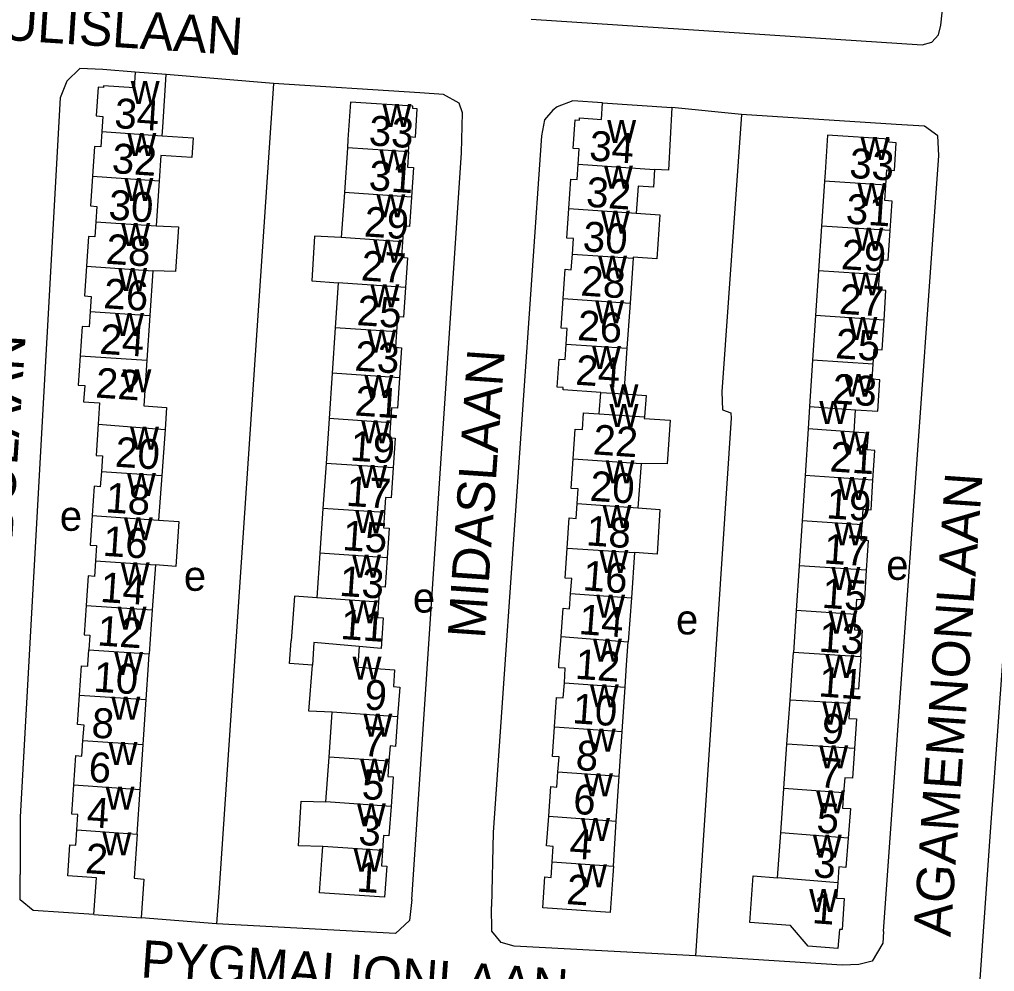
# Model space of a CAD drawing. Extents: x 161773 to 163836, y 384796 to 386521.
# Drawn here: x 162100.7 to 162231.1, y 385459 to 385586.3 of the extents above; entities that cross this region are included whole.
import ezdxf

# ---------------------------------------------------------------- set-up
doc = ezdxf.new("R2010")
doc.units = 0
for name, color, linetype in [('BLT_Basislijn', 7, 'Continuous'), ('BLT_Bebouwing', 7, 'Continuous'), ('BLT_Centroide', 7, 'Continuous'), ('BLT_Huisnummer', 7, 'Continuous'), ('BLT_Huisnummer_ tussenligend', 7, 'Continuous'), ('BLT_Onderverdeling_panden', 7, 'Continuous'), ('BLT_Straatnaam', 7, 'Continuous')]:
    doc.layers.add(name, color=color, linetype=linetype)

msp = doc.modelspace()

# ---------------------------------------------------------------- linework, layer by layer
at = {"layer": 'BLT_Basislijn'}
for p, q in [((162134.64, 385577.69), (162127.4, 385470.16)), ((162230.63, 385478.94), (162230.98, 385483.73)), ((162229.61, 385464.38), (162230.63, 385478.94)), ((162127.4, 385470.16), (162127.01, 385465.4)), ((162227.1, 385428.51), (162229.61, 385464.38))]:
    msp.add_line(p, q, dxfattribs=at)
for points in [[(162169.1, 385586.33), (162221.38, 385582.88), (162222.67, 385583.23), (162223.56, 385584.21), (162223.9, 385585.5), (162224.18, 385588.39), (162225.39, 385606.24)], [(162116.15, 385579.21), (162111.84, 385579.56), (162108.77, 385579.7), (162106.99, 385578.01), (162106.1, 385575.79), (162100.77, 385479.69), (162100.75, 385471.99)], [(162134.64, 385577.69), (162120.31, 385578.93)], [(162159.92, 385573.8), (162159.47, 385575.09), (162157.4, 385576.26), (162154.2, 385576.48), (162134.64, 385577.69)], [(162178.64, 385575.12), (162174.67, 385575.38), (162172.6, 385574.61), (162172, 385574.16), (162170.89, 385572.86), (162170.47, 385570.73)], [(162197.21, 385573.57), (162187.91, 385574.49)], [(162153.13, 385468.63), (162159.77, 385568.46), (162159.92, 385573.8)], [(162197.21, 385573.57), (162194.59, 385536.51), (162194.7, 385534.11), (162195.8, 385533.7), (162195.83, 385532.98), (162191.08, 385461.11)], [(162223.46, 385570.7), (162221.71, 385572), (162217.92, 385572.25), (162197.21, 385573.57)], [(162170.47, 385570.73), (162164.04, 385477.58), (162163.78, 385467.71)], [(162216.22, 385464.38), (162223.62, 385568.08), (162223.46, 385570.7)], [(162230.98, 385483.73), (162234.59, 385533.9), (162235.86, 385535.65), (162236.97, 385536.24)], [(162110.62, 385466.63), (162102.51, 385467.15), (162100.77, 385468.61), (162100.75, 385471.99)], [(162153.13, 385468.63), (162152.85, 385465.84), (162150.95, 385464.11), (162127.01, 385465.4)], [(162191.08, 385461.11), (162166.85, 385462.41), (162165.1, 385462.88), (162163.83, 385464.41), (162163.78, 385467.71)], [(162127.01, 385465.4), (162116.94, 385466.21)], [(162216.22, 385464.38), (162216.14, 385462.79), (162214.71, 385460.4), (162212.93, 385459.94), (162210.69, 385459.84), (162191.08, 385461.11)]]:
    msp.add_lwpolyline(points, dxfattribs=at)
at = {"layer": 'BLT_Bebouwing'}
for p, q in [((162144.52, 385569.12), (162144.12, 385563.13)), ((162119.35, 385564.72), (162118.94, 385558.7)), ((162208.32, 385564.64), (162207.93, 385558.65)), ((162144.12, 385563.13), (162143.71, 385557.12)), ((162207.93, 385558.65), (162207.53, 385552.66)), ((162182.73, 385554.35), (162182.32, 385548.34)), ((162118.53, 385552.68), (162118.13, 385546.68)), ((162207.53, 385552.66), (162207.14, 385546.68)), ((162143.3, 385551.07), (162142.9, 385545.05)), ((162182.32, 385548.34), (162181.91, 385542.34)), ((162118.13, 385546.68), (162117.73, 385540.72)), ((162207.14, 385546.68), (162206.74, 385540.72)), ((162142.9, 385545.05), (162142.48, 385538.97)), ((162181.91, 385542.34), (162181.5, 385536.21)), ((162117.73, 385540.72), (162117.31, 385534.62)), ((162206.74, 385540.72), (162206.34, 385534.54)), ((162142.48, 385538.97), (162142.07, 385532.92)), ((162178.21, 385533.56), (162178.4, 385536.42)), ((162111.4, 385535.02), (162111.2, 385532.17)), ((162206.34, 385534.54), (162206.14, 385531.57)), ((162212.39, 385532.61), (162212.49, 385534.11)), ((162142.07, 385532.92), (162141.67, 385526.92)), ((162206.14, 385531.57), (162205.73, 385525.3)), ((162141.67, 385526.92), (162141.26, 385520.92)), ((162183.8, 385526.93), (162183.38, 385521)), ((162119.71, 385525.32), (162119.29, 385519.35)), ((162205.73, 385525.3), (162205.33, 385519.26)), ((162141.26, 385520.92), (162140.86, 385514.94)), ((162205.33, 385519.26), (162204.93, 385513.25)), ((162140.86, 385514.94), (162140.45, 385508.94)), ((162182.94, 385515), (162182.51, 385508.97)), ((162118.87, 385513.35), (162118.44, 385507.34)), ((162204.93, 385513.25), (162204.53, 385507.26)), ((162182.51, 385508.97), (162182.09, 385503.1)), ((162118.44, 385507.34), (162118.03, 385501.46)), ((162204.53, 385507.26), (162204.16, 385501.67)), ((162181.28, 385491.09), (162181.67, 385497.02)), ((162117.21, 385489.34), (162117.61, 385495.35)), ((162203.31, 385489.42), (162203.72, 385495.27)), ((162142.07, 385487.68), (162142.48, 385493.68)), ((162180.88, 385485.12), (162181.28, 385491.09)), ((162116.81, 385483.36), (162117.21, 385489.34)), ((162202.89, 385483.47), (162203.31, 385489.42)), ((162141.65, 385481.69), (162142.07, 385487.68)), ((162180.49, 385479.13), (162180.88, 385485.12)), ((162116.41, 385477.39), (162116.81, 385483.36)), ((162202.47, 385477.56), (162202.89, 385483.47)), ((162180.09, 385473.09), (162180.49, 385479.13)), ((162202.04, 385471.54), (162202.47, 385477.56)), ((162149.5, 385468.95), (162140.81, 385469.55)), ((162179.68, 385466.9), (162170.64, 385467.53)), ((162110.62, 385466.63), (162116.94, 385466.21))]:
    msp.add_line(p, q, dxfattribs=at)
for points in [[(162116.15, 385579.21), (162116.01, 385577.14), (162111.92, 385577.42), (162111.9, 385577.18), (162111.21, 385577.23), (162110.95, 385573.37), (162111.83, 385573.31), (162111.69, 385571.28)], [(162120.31, 385578.93), (162116.15, 385579.21)], [(162119.75, 385570.73), (162119.83, 385571.87), (162120.31, 385578.93)], [(162152.7, 385568.57), (162152.83, 385570.61), (162153.62, 385570.55), (162153.88, 385574.34), (162153.28, 385574.38), (162153.3, 385574.66), (162144.94, 385575.23), (162144.6, 385570.24), (162144.52, 385569.12)], [(162175.39, 385566.92), (162175.53, 385568.97), (162174.71, 385569.03), (162174.97, 385572.87), (162175.56, 385572.83), (162175.58, 385573.11), (162178.49, 385572.91), (162178.64, 385575.12)], [(162178.64, 385575.12), (162187.91, 385574.49)], [(162187.91, 385574.49), (162187.46, 385566.12), (162185.61, 385566.22)], [(162111.69, 385571.28), (162111.55, 385569.24), (162110.73, 385569.29), (162110.46, 385565.32)], [(162119.75, 385570.73), (162123.91, 385570.45), (162123.73, 385567.8), (162119.57, 385568.08), (162119.35, 385564.72)], [(162216.52, 385564.1), (162216.66, 385566.15), (162217.68, 385566.09), (162217.93, 385569.79), (162216.93, 385569.86), (162216.96, 385570.27), (162208.73, 385570.82), (162208.4, 385565.83), (162208.32, 385564.64)], [(162152.7, 385568.57), (162152.56, 385566.52), (162153.35, 385566.47), (162153.09, 385562.53)], [(162174.14, 385560.98), (162174.41, 385564.93), (162175.26, 385564.87), (162175.39, 385566.92)], [(162185.61, 385566.22), (162185.45, 385563.85), (162183.39, 385563.99), (162183.14, 385560.37)], [(162110.46, 385565.32), (162110.19, 385561.35), (162111.04, 385561.29), (162110.9, 385559.24)], [(162217.11, 385558.04), (162217.37, 385561.99), (162216.39, 385562.05), (162216.52, 385564.1)], [(162153.09, 385562.53), (162152.82, 385558.59), (162152.03, 385558.64), (162151.89, 385556.56)], [(162174.61, 385554.9), (162174.75, 385556.98), (162173.87, 385557.04), (162174.14, 385560.98)], [(162183.14, 385560.37), (162186.3, 385560.16), (162185.9, 385554.29), (162182.74, 385554.5), (162182.73, 385554.35)], [(162110.9, 385559.24), (162110.76, 385557.2), (162109.9, 385557.26), (162109.64, 385553.29)], [(162118.94, 385558.7), (162121.94, 385558.53), (162121.56, 385552.56), (162118.53, 385552.68)], [(162143.71, 385557.12), (162140.14, 385557.32), (162139.77, 385551.35), (162143.3, 385551.07)], [(162215.67, 385552.12), (162215.81, 385554.16), (162216.84, 385554.09), (162217.11, 385558.04)], [(162151.89, 385556.56), (162151.75, 385554.49), (162152.55, 385554.43), (162152.28, 385550.46)], [(162173.38, 385548.95), (162173.64, 385552.88), (162174.47, 385552.82), (162174.61, 385554.9)], [(162109.64, 385553.29), (162109.37, 385549.31), (162110.25, 385549.25), (162110.11, 385547.22)], [(162216.29, 385546.07), (162216.55, 385550.02), (162215.54, 385550.09), (162215.67, 385552.12)], [(162152.28, 385550.46), (162152.01, 385546.49), (162151.22, 385546.54), (162151.08, 385544.5)], [(162173.79, 385542.89), (162173.93, 385544.96), (162173.11, 385545.02), (162173.38, 385548.95)], [(162110.11, 385547.22), (162109.98, 385545.19), (162109.07, 385545.25), (162108.81, 385541.32)], [(162214.84, 385540.19), (162214.98, 385542.2), (162216.03, 385542.12), (162216.29, 385546.07)], [(162151.08, 385544.5), (162150.94, 385542.46), (162151.77, 385542.4), (162151.49, 385538.36)], [(162178.4, 385536.42), (162173.38, 385536.76), (162173.4, 385537.08), (162172.59, 385537.14), (162172.85, 385540.88), (162173.65, 385540.83), (162173.79, 385542.89)], [(162108.81, 385541.32), (162108.54, 385537.4), (162109.4, 385537.34), (162109.26, 385535.17), (162111.4, 385535.02)], [(162212.49, 385534.11), (162215.45, 385533.92), (162215.73, 385538.11), (162214.71, 385538.18), (162214.84, 385540.19)], [(162151.49, 385538.36), (162151.22, 385534.32), (162150.41, 385534.38), (162150.28, 385532.36)], [(162181.5, 385536.21), (162184.46, 385536.02), (162184.25, 385533.17)], [(162117.31, 385534.62), (162120.35, 385534.42), (162120.15, 385531.48)], [(162174.71, 385527.55), (162174.98, 385531.52), (162175.95, 385531.45), (162176.11, 385533.71), (162178.21, 385533.56)], [(162150.28, 385532.36), (162150.14, 385530.35), (162150.93, 385530.3), (162150.66, 385526.32)], [(162184.25, 385533.17), (162184.23, 385532.92), (162187.68, 385532.73), (162187.31, 385526.86), (162183.8, 385526.93)], [(162212.29, 385531.1), (162212.39, 385532.61)], [(162111.2, 385532.17), (162110.92, 385527.98), (162111.77, 385527.92), (162111.63, 385525.87)], [(162120.15, 385531.48), (162119.71, 385525.32)], [(162214.81, 385524.7), (162215.07, 385528.66), (162214.05, 385528.73), (162214.2, 385530.97), (162212.29, 385531.1)], [(162175.25, 385521.55), (162175.38, 385523.53), (162174.44, 385523.59), (162174.71, 385527.55)], [(162111.63, 385525.87), (162111.49, 385523.82), (162110.68, 385523.87), (162110.41, 385519.95)], [(162150.66, 385526.32), (162150.39, 385522.33), (162149.62, 385522.39), (162149.48, 385520.36)], [(162213.37, 385518.73), (162213.51, 385520.81), (162214.55, 385520.74), (162214.81, 385524.7)], [(162173.91, 385515.62), (162174.19, 385519.64), (162175.11, 385519.58), (162175.25, 385521.55)], [(162183.38, 385521), (162186.32, 385520.79), (162185.93, 385514.79), (162182.94, 385515)], [(162110.41, 385519.95), (162110.15, 385516.02), (162110.97, 385515.97), (162110.83, 385513.89)], [(162119.29, 385519.35), (162121.99, 385519.16), (162121.58, 385513.16), (162118.87, 385513.35)], [(162149.48, 385520.36), (162149.34, 385518.34), (162150.13, 385518.29), (162149.86, 385514.33)], [(162213.96, 385512.66), (162214.22, 385516.59), (162213.23, 385516.65), (162213.37, 385518.73)], [(162174.38, 385509.53), (162174.52, 385511.54), (162173.64, 385511.6), (162173.91, 385515.62)], [(162149.86, 385514.33), (162149.6, 385510.38), (162148.82, 385510.43), (162148.68, 385508.38)], [(162110.83, 385513.89), (162110.69, 385511.82), (162109.85, 385511.88), (162109.58, 385507.94)], [(162212.53, 385506.73), (162212.67, 385508.8), (162213.7, 385508.73), (162213.96, 385512.66)], [(162140.45, 385508.94), (162137.47, 385509.2), (162137.03, 385503.22)], [(162173.11, 385503.78), (162173.4, 385507.57), (162174.24, 385507.51), (162174.38, 385509.53)], [(162109.58, 385507.94), (162109.32, 385504), (162110.09, 385503.97), (162109.96, 385501.99)], [(162148.68, 385508.38), (162148.54, 385506.34), (162149.31, 385506.28), (162149.04, 385502.2), (162146.1, 385502.45)], [(162213.18, 385501.08), (162213.42, 385504.6), (162212.39, 385504.66), (162212.53, 385506.73)], [(162173.54, 385497.58), (162173.67, 385499.56), (162172.79, 385499.62), (162172.82, 385500), (162173.11, 385503.78)], [(162139.84, 385499.95), (162136.78, 385500.18), (162137.03, 385503.22)], [(162146.1, 385502.45), (162145.91, 385500), (162145.89, 385499.68)], [(162181.67, 385497.02), (162181.87, 385500), (162182.09, 385503.1)], [(162108.7, 385495.94), (162108.96, 385499.88), (162109.81, 385499.82), (162109.83, 385500), (162109.96, 385501.99)], [(162117.61, 385495.35), (162117.93, 385500), (162118.03, 385501.46)], [(162203.72, 385495.27), (162204.05, 385499.9), (162204.16, 385501.67)], [(162213.18, 385501.08), (162213.1, 385499.95), (162212.89, 385496.74), (162211.83, 385496.8), (162211.72, 385494.82)], [(162142.48, 385493.68), (162139.38, 385493.8), (162139.84, 385499.95)], [(162145.89, 385499.68), (162150.84, 385499.34), (162150.69, 385497.1), (162151.52, 385497.04), (162151.24, 385493.07)], [(162172.24, 385491.71), (162172.51, 385495.66), (162173.4, 385495.6), (162173.54, 385497.58)], [(162109.17, 385489.88), (162109.31, 385491.95), (162108.44, 385492.01), (162108.7, 385495.94)], [(162211.72, 385494.82), (162211.6, 385492.84), (162212.62, 385492.78), (162212.35, 385488.81)], [(162151.24, 385493.07), (162150.97, 385489.11), (162150.23, 385489.16), (162150.09, 385487.12)], [(162172.69, 385485.69), (162172.83, 385487.71), (162171.97, 385487.77), (162172.24, 385491.71)], [(162107.96, 385483.95), (162108.22, 385487.87), (162109.03, 385487.81), (162109.17, 385489.88)], [(162212.35, 385488.81), (162212.08, 385484.84), (162211.03, 385484.91), (162210.88, 385482.88)], [(162150.09, 385487.12), (162149.95, 385485.09), (162150.64, 385485.05), (162150.36, 385481.09)], [(162171.45, 385479.76), (162171.73, 385483.73), (162172.55, 385483.67), (162172.69, 385485.69)], [(162108.36, 385477.93), (162108.5, 385479.98), (162107.7, 385480.03), (162107.96, 385483.95)], [(162210.88, 385482.88), (162210.73, 385480.86), (162211.79, 385480.78), (162211.48, 385476.85)], [(162141.24, 385475.73), (162138.01, 385475.82), (162138.34, 385481.79), (162141.65, 385481.69)], [(162150.36, 385481.09), (162150.09, 385477.13), (162149.36, 385477.18), (162149.22, 385475.17)], [(162171.9, 385473.66), (162172.05, 385475.73), (162171.17, 385475.79), (162171.45, 385479.76)], [(162107.14, 385471.81), (162107.42, 385475.93), (162108.23, 385475.88), (162108.36, 385477.93)], [(162116.41, 385477.39), (162116.02, 385471.47), (162117.32, 385471.37), (162116.94, 385466.21)], [(162211.48, 385476.85), (162211.17, 385472.92), (162210.26, 385472.99), (162210.09, 385470.85)], [(162140.81, 385469.55), (162141.15, 385474.54), (162141.24, 385475.73)], [(162149.22, 385475.17), (162149.08, 385473.16), (162149.79, 385473.11), (162149.5, 385468.95)], [(162170.64, 385467.53), (162170.92, 385471.66), (162171.76, 385471.6), (162171.9, 385473.66)], [(162180.09, 385473.09), (162180.01, 385471.89), (162179.68, 385466.9)], [(162110.62, 385466.63), (162110.96, 385471.55), (162107.14, 385471.81)], [(162210.68, 385464.63), (162210.33, 385464.65), (162210.13, 385462.09), (162206.14, 385462.4), (162203.8, 385465.16), (162198.34, 385465.58), (162198.77, 385471.82), (162202.04, 385471.54)], [(162210.09, 385470.85), (162209.93, 385468.82), (162210.96, 385468.75), (162210.68, 385464.63)]]:
    msp.add_lwpolyline(points, dxfattribs=at)
at = {"layer": 'BLT_Onderverdeling_panden'}
for p, q in [((162111.69, 385571.28), (162119.75, 385570.73)), ((162152.7, 385568.57), (162144.52, 385569.12)), ((162175.39, 385566.92), (162185.61, 385566.22)), ((162110.46, 385565.32), (162119.35, 385564.72)), ((162216.52, 385564.1), (162208.32, 385564.64)), ((162153.09, 385562.53), (162144.12, 385563.13)), ((162174.14, 385560.98), (162183.14, 385560.37)), ((162110.9, 385559.24), (162118.94, 385558.7)), ((162217.11, 385558.04), (162207.93, 385558.65)), ((162151.89, 385556.56), (162143.71, 385557.12)), ((162174.61, 385554.9), (162182.73, 385554.35)), ((162109.64, 385553.29), (162118.53, 385552.68)), ((162215.67, 385552.12), (162207.53, 385552.66)), ((162152.28, 385550.46), (162143.3, 385551.07)), ((162173.38, 385548.95), (162182.32, 385548.34)), ((162110.11, 385547.22), (162118.13, 385546.68)), ((162216.29, 385546.07), (162207.14, 385546.68)), ((162151.08, 385544.5), (162142.9, 385545.05)), ((162173.79, 385542.89), (162181.91, 385542.34)), ((162108.81, 385541.32), (162117.73, 385540.72)), ((162214.84, 385540.19), (162206.74, 385540.72)), ((162151.49, 385538.36), (162142.48, 385538.97)), ((162178.4, 385536.42), (162181.5, 385536.21)), ((162178.21, 385533.56), (162184.25, 385533.17)), ((162206.34, 385534.54), (162212.49, 385534.11)), ((162150.28, 385532.36), (162142.07, 385532.92)), ((162111.2, 385532.17), (162120.15, 385531.48)), ((162212.29, 385531.1), (162206.14, 385531.57)), ((162174.71, 385527.55), (162183.8, 385526.93)), ((162111.63, 385525.87), (162119.71, 385525.32)), ((162150.66, 385526.32), (162141.67, 385526.92)), ((162214.81, 385524.7), (162205.73, 385525.3)), ((162149.48, 385520.36), (162141.26, 385520.92)), ((162175.25, 385521.55), (162183.38, 385521)), ((162110.41, 385519.95), (162119.29, 385519.35)), ((162213.37, 385518.73), (162205.33, 385519.26)), ((162173.91, 385515.62), (162182.94, 385515)), ((162149.86, 385514.33), (162140.86, 385514.94)), ((162110.83, 385513.89), (162118.87, 385513.35)), ((162213.96, 385512.66), (162204.93, 385513.25)), ((162148.68, 385508.38), (162140.45, 385508.94)), ((162174.38, 385509.53), (162182.51, 385508.97)), ((162109.58, 385507.94), (162118.44, 385507.34)), ((162212.53, 385506.73), (162204.53, 385507.26)), ((162173.11, 385503.78), (162182.09, 385503.1)), ((162109.96, 385501.99), (162118.03, 385501.46)), ((162213.18, 385501.08), (162204.16, 385501.67)), ((162173.54, 385497.58), (162181.67, 385497.02)), ((162108.7, 385495.94), (162117.61, 385495.35)), ((162211.72, 385494.82), (162203.72, 385495.27)), ((162151.24, 385493.07), (162142.48, 385493.68)), ((162172.24, 385491.71), (162181.28, 385491.09)), ((162109.17, 385489.88), (162117.21, 385489.34)), ((162212.35, 385488.81), (162203.31, 385489.42)), ((162150.09, 385487.12), (162142.07, 385487.68)), ((162172.69, 385485.69), (162180.88, 385485.12)), ((162107.96, 385483.95), (162116.81, 385483.36)), ((162210.88, 385482.88), (162202.89, 385483.47)), ((162150.36, 385481.09), (162141.65, 385481.69)), ((162171.45, 385479.76), (162180.49, 385479.13)), ((162108.36, 385477.93), (162116.41, 385477.39)), ((162211.48, 385476.85), (162202.47, 385477.56)), ((162149.22, 385475.17), (162141.24, 385475.73)), ((162171.9, 385473.66), (162180.09, 385473.09)), ((162210.09, 385470.85), (162202.04, 385471.54))]:
    msp.add_line(p, q, dxfattribs=at)
msp.add_lwpolyline([(162146.1, 385502.45), (162140.05, 385502.97), (162139.84, 385499.95)], dxfattribs=at)

# ---------------------------------------------------------------- texts
at = {"layer": 'BLT_Centroide'}
for s, p in [('w', (162115.55, 385574.97)), ('w', (162149.22, 385571.91)), ('w', (162179.27, 385569.75)), ('w', (162115.1, 385568)), ('w', (162213.14, 385567.47)), ('w', (162148.8, 385565.81)), ('w', (162178.84, 385563.66)), ('w', (162114.7, 385562)), ('w', (162212.72, 385561.34)), ('w', (162148.4, 385559.84)), ('w', (162178.44, 385557.66)), ('w', (162114.28, 385555.97)), ('w', (162212.32, 385555.38)), ('w', (162147.99, 385553.78)), ('w', (162178.05, 385551.62)), ('w', (162113.88, 385549.97)), ('w', (162211.91, 385549.38)), ('w', (162147.59, 385547.78)), ('w', (162177.65, 385545.66)), ('w', (162113.46, 385543.97)), ('w', (162211.52, 385543.44)), ('w', (162147.2, 385541.72)), ('w', (162177.24, 385539.56)), ('w', (162114.45, 385536.44)), ('w', (162210.94, 385535.83)), ('w', (162146.79, 385535.66)), ('w', (162179.58, 385534.42)), ('w', (162179.58, 385531.78)), ('w', (162207.63, 385532.21)), ('w', (162146.36, 385529.62)), ('w', (162115.46, 385528.75)), ('w', (162210.47, 385528.12)), ('w', (162179.05, 385524.28)), ('w', (162145.97, 385523.66)), ('w', (162115.05, 385522.59)), ('w', (162210.07, 385522.03)), ('e', (162106.07, 385517.92)), ('w', (162145.56, 385517.62)), ('w', (162178.64, 385518.28)), ('w', (162114.64, 385516.66)), ('w', (162209.64, 385515.97)), ('w', (162178.22, 385512.28)), ('w', (162145.16, 385511.66)), ('e', (162216.59, 385511.36)), ('w', (162114.22, 385510.62)), ('e', (162122.66, 385509.9)), ('w', (162209.25, 385510)), ('e', (162153.28, 385506.99)), ('w', (162177.8, 385506.31)), ('w', (162113.8, 385504.69)), ('w', (162144.74, 385505.56)), ('e', (162188.47, 385504.07)), ('w', (162208.86, 385504.16)), ('w', (162177.37, 385500.41)), ('w', (162113.35, 385498.66)), ('w', (162145.22, 385498.03)), ('w', (162208.46, 385498.25)), ('w', (162176.95, 385494.34)), ('w', (162112.96, 385492.66)), ('w', (162208.03, 385492.03)), ('w', (162146.66, 385490.41)), ('w', (162176.55, 385488.41)), ('w', (162112.59, 385486.62)), ('w', (162207.62, 385486.16)), ('w', (162146.22, 385484.38)), ('w', (162176.17, 385482.41)), ('w', (162112.19, 385480.66)), ('w', (162207.2, 385480.16)), ('w', (162145.8, 385478.44)), ('w', (162175.77, 385476.44)), ('w', (162111.77, 385474.56)), ('w', (162206.76, 385474.22)), ('w', (162145.37, 385472.34)), ('w', (162175.37, 385470.28)), ('w', (162206.28, 385466.97))]:
    msp.add_text(s, height=4, dxfattribs=at).set_placement(p)
at = {"layer": 'BLT_Huisnummer'}
for s, rotation, p in [('34', 356.119, (162113.29, 385571.78)), ('33', 356.2314, (162147.32, 385569.46)), ('34', 356.1067, (162176.79, 385567.43)), ('33', 356.2314, (162211.57, 385565.11)), ('30', 356.1292, (162112.51, 385559.53)), ('29', 356.127, (162146.68, 385557.28)), ('30', 356.1045, (162175.93, 385555.31)), ('29', 356.222, (162210.48, 385552.91)), ('26', 356.1309, (162111.84, 385547.69)), ('25', 356.1266, (162145.71, 385545.43)), ('26', 356.097, (162175.2, 385543.43)), ('25', 356.2246, (162209.7, 385541)), ('22', 356.1255, (162110.76, 385535.75)), ('21', 356.126, (162145.45, 385533.35)), ('22', 356.1044, (162177.29, 385528.15)), ('21', 356.2162, (162208.95, 385525.87)), ('17', 356.1192, (162144.27, 385521.27)), ('18', 356.1337, (162112.1, 385520.4)), ('18', 356.1083, (162176.38, 385515.99)), ('17', 356.2183, (162208.14, 385513.57)), ('13', 356.0363, (162143.37, 385509.24)), ('14', 356.1314, (162111.4, 385508.42)), ('14', 355.6262, (162175.39, 385504.13)), ('13', 356.1472, (162207.47, 385501.78)), ('10', 356.1812, (162110.48, 385496.44)), ('9', 356.0311, (162146.7, 385494.07)), ('10', 356.0428, (162174.54, 385492.21)), ('9', 355.7702, (162207.83, 385489.58)), ('6', 356.1816, (162109.83, 385484.39)), ('5', 356.0311, (162146.37, 385482.09)), ('6', 356.0374, (162174.63, 385480.11)), ('5', 355.7702, (162207.17, 385477.62)), ('2', 356.1769, (162109.4, 385472.18)), ('1', 356.0329, (162145.68, 385469.71)), ('2', 356.0328, (162173.73, 385468.04)), ('1', 355.5989, (162206.6, 385465.49))]:
    msp.add_text(s, height=4, rotation=rotation, dxfattribs=at).set_placement(p)
at = {"layer": 'BLT_Huisnummer_ tussenligend'}
for s, rotation, p in [('32', 356.1812, (162112.96, 385565.75)), ('31', 356.0329, (162147.31, 385563.46)), ('32', 356.1045, (162176.37, 385561.25)), ('31', 356.222, (162211.11, 385559)), ('28', 356.1812, (162112.15, 385553.63)), ('27', 356.0329, (162146.27, 385551.41)), ('28', 356.097, (162175.64, 385549.38)), ('27', 356.2246, (162210.2, 385546.95)), ('24', 356.1812, (162111.31, 385541.6)), ('23', 356.0329, (162145.42, 385539.35)), ('24', 356.1044, (162174.95, 385537.46)), ('23', 356.2162, (162209.27, 385534.95)), ('19', 356.0329, (162144.81, 385527.32)), ('20', 356.1812, (162113.38, 385526.5)), ('20', 356.1083, (162176.86, 385521.95)), ('19', 356.2183, (162208.49, 385519.6)), ('15', 356.0329, (162143.79, 385515.35)), ('16', 356.1812, (162111.75, 385514.59)), ('16', 355.6262, (162175.91, 385509.99)), ('15', 356.1472, (162207.9, 385507.64)), ('12', 356.1812, (162111.01, 385502.61)), ('11', 356.0329, (162143.53, 385503.47)), ('12', 356.0428, (162174.9, 385498.15)), ('11', 355.7702, (162207.45, 385495.8)), ('8', 356.1816, (162110.23, 385490.3)), ('7', 356.0329, (162146.5, 385487.84)), ('8', 356.0374, (162174.98, 385485.97)), ('7', 355.7702, (162207.51, 385483.66)), ('4', 356.1769, (162109.59, 385478.35)), ('3', 356.0329, (162145.93, 385475.96)), ('4', 356.0328, (162174.15, 385474.16)), ('3', 355.5989, (162206.75, 385471.64))]:
    msp.add_text(s, height=4, rotation=rotation, dxfattribs=at).set_placement(p)
at = {"layer": 'BLT_Straatnaam'}
for s, rotation, p in [('AULISLAAN', 356.2653, (162093.7, 385583.87)), ('DIDOLAAN', 86.241, (162099.27, 385509.94)), ('MIDASLAAN', 86.0483, (162162.92, 385503.43)), ('AGAMEMNONLAAN', 86.0382, (162225.18, 385463.58)), ('PYGMALIONLAAN', 356.0339, (162116.8, 385458.25))]:
    msp.add_text(s, height=5, rotation=rotation, dxfattribs=at).set_placement(p)

doc.saveas('drawing.dxf')
